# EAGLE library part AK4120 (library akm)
Sample Rate Converter with Mixer/Volume 24-Bit, 96 kHz
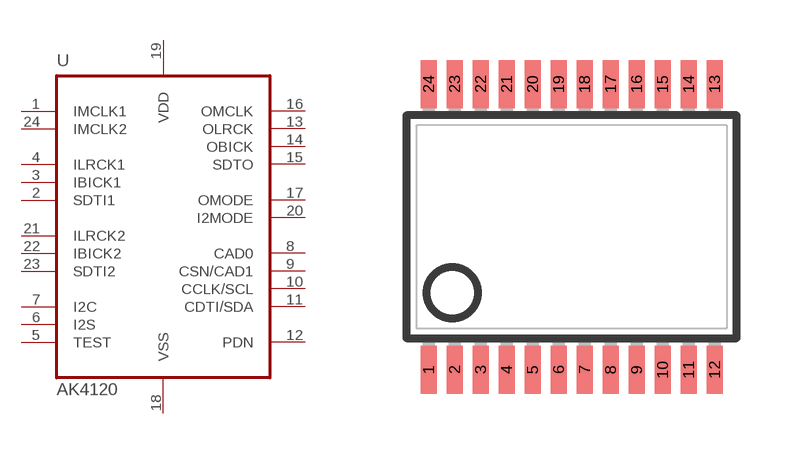
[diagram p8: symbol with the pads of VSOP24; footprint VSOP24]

Designator prefix U

## AK4120  [VSOP24]
1  IMCLK1  in
2  SDTI1  in
3  IBICK1  in
4  ILRCK1  in
5  TEST
6  I2S  in
7  I2C  in
8  CAD0  in
9  CSN/CAD1  in
10  CCLK/SCL  in
11  CDTI/SDA
12  PDN  in
13  OLRCK
14  OBICK
15  SDTO  out
16  OMCLK  in
17  OMODE
18  VSS  pwr
19  VDD  pwr
20  I2MODE  in
21  ILRCK2
22  IBICK2
23  SDTI2  in
24  IMCLK2  in

## Footprint VSOP24 (pad centres in mm)
VSOP24 7.8 x 5.6 mm, pitch .65 mm
smd 0.4 x 1.2: 1 -3.575,-3.57; 2 -2.925,-3.57; 3 -2.275,-3.57; 4 -1.625,-3.57; 5 -0.975,-3.57; 6 -0.325,-3.57; 7 0.325,-3.57; 8 0.975,-3.57; 9 1.625,-3.57; 10 2.275,-3.57; 11 2.925,-3.57; 12 3.575,-3.57; 13 3.575,3.57; 14 2.925,3.57; 15 2.275,3.57; 16 1.625,3.57; 17 0.975,3.57; 18 0.325,3.57; 19 -0.325,3.57; 20 -0.975,3.57; 21 -1.625,3.57; 22 -2.275,3.57; 23 -2.925,3.57; 24 -3.575,3.57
